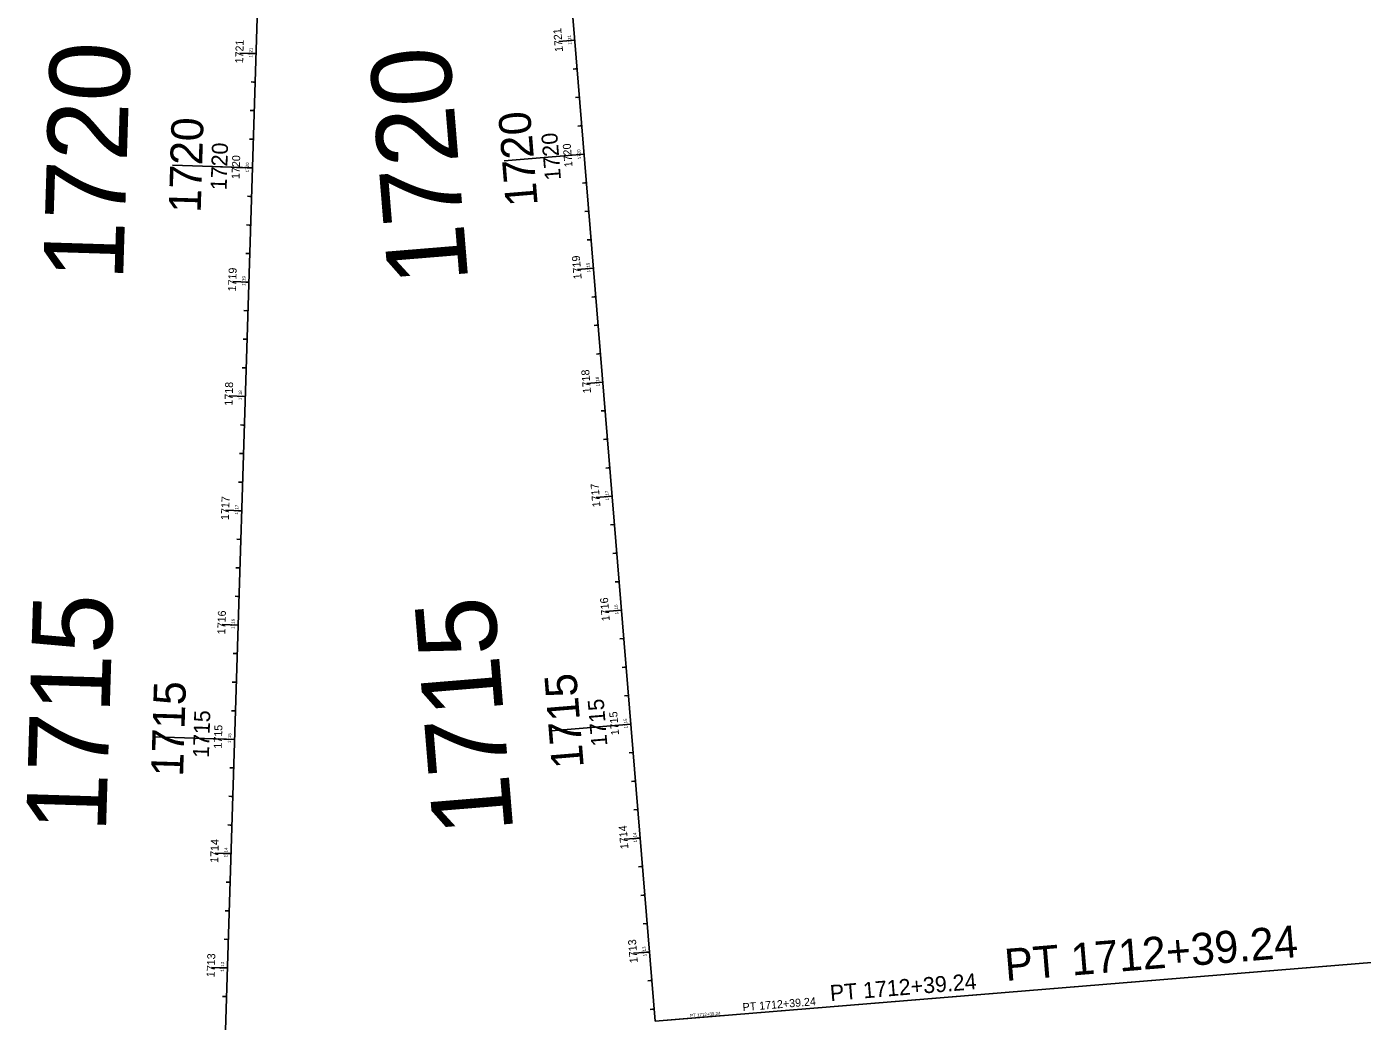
# Model space of a CAD drawing. Extents: x 353835 to 363333, y 126218 to 205387.
# Drawn here: x 361213 to 362381, y 130454 to 131324 of the extents above; entities that cross this region are included whole.
import ezdxf

# ---------------------------------------------------------------- set-up
doc = ezdxf.new("R2010")
doc.units = 0
for name, color, linetype in [('P_ALI_100_PIData', 7, 'Continuous'), ('P_ALI_100_Sta', 7, 'Continuous'), ('P_ALI_100_Tic', 7, 'Continuous'), ('P_ALI_20', 7, 'Continuous'), ('P_ALI_200_PIData', 7, 'Continuous'), ('P_ALI_200_Sta', 7, 'Continuous'), ('P_ALI_200_Tic', 7, 'Continuous'), ('P_ALI_20_PIData', 7, 'Continuous'), ('P_ALI_20_Sta', 7, 'Continuous'), ('P_ALI_20_Tic', 7, 'Continuous'), ('P_ALI_500_PIData', 7, 'Continuous'), ('P_ALI_500_Sta', 7, 'Continuous'), ('P_ALI_50_PIData', 7, 'Continuous'), ('P_ALI_50_Sta', 7, 'Continuous'), ('P_ALI_50_Tic', 7, 'Continuous')]:
    doc.layers.add(name, color=color, linetype=linetype)

msp = doc.modelspace()

# ---------------------------------------------------------------- linework, layer by layer
for points in [[(361692.5, 131312), (361692.5, 131312)], [(361708.9, 131112.6), (361708.9, 131112.6)], [(361717.1, 131013), (361717.1, 131013)], [(361725.2, 130913.3), (361725.3, 130913.3)], [(361733.4, 130813.6), (361733.4, 130813.6)], [(361749.8, 130614.3), (361749.8, 130614.3)], [(361757.9, 130514.6), (361758, 130514.6)]]:
    msp.add_lwpolyline(points)
at = {"layer": 'P_ALI_100_PIData'}
for points in [[(361762.9, 130454.1), (362061.9, 130478.6)], [(361762.9, 130454.1), (361822.7, 130459)]]:
    msp.add_lwpolyline(points, dxfattribs=at)
at = {"layer": 'P_ALI_100_Tic'}
for points in [[(361685.6, 131311.4), (361692.5, 131312)], [(361406.7, 131300.5), (361413.7, 131300.3)], [(361630.9, 131206.6), (361700.7, 131212.3)], [(361686.8, 131211.1), (361700.7, 131212.3)], [(361340.6, 131202.6), (361410.6, 131200.4)], [(361396.6, 131200.8), (361410.6, 131200.4)], [(361701.9, 131112.1), (361708.9, 131112.6)], [(361400.5, 131100.6), (361407.5, 131100.4)], [(361710.1, 131012.4), (361717.1, 131013)], [(361397.3, 131000.7), (361404.3, 131000.5)], [(361718.3, 130912.7), (361725.2, 130913.3)], [(361394.2, 130900.7), (361401.2, 130900.5)], [(361726.4, 130813.1), (361733.4, 130813.6)], [(361391.1, 130800.8), (361398.1, 130800.6)], [(361671.8, 130708.2), (361741.6, 130714)], [(361727.6, 130712.8), (361741.6, 130714)], [(361325, 130702.8), (361395, 130700.6)], [(361381, 130701.1), (361395, 130700.6)], [(361742.8, 130613.7), (361749.8, 130614.3)], [(361384.9, 130600.9), (361391.9, 130600.7)], [(361751, 130514.1), (361757.9, 130514.6)], [(361381.7, 130500.9), (361388.7, 130500.7)]]:
    msp.add_lwpolyline(points, dxfattribs=at)
at = {"layer": 'P_ALI_20'}
for p, q in [((361371.2, 129938.3), (361462, 132847.8)), ((361762.9, 130454.1), (361568.2, 132827.2))]:
    msp.add_line(p, q, dxfattribs=at)
at = {"layer": 'P_ALI_200_PIData'}
msp.add_lwpolyline([(361762.9, 130454.1), (362360.9, 130503.1)], dxfattribs=at)
at = {"layer": 'P_ALI_200_Tic'}
for points in [[(361678.6, 131310.8), (361692.5, 131312)], [(361399.7, 131300.8), (361413.7, 131300.3)], [(361672.8, 131210), (361700.7, 131212.3)], [(361382.6, 131201.3), (361410.6, 131200.4)], [(361694.9, 131111.5), (361708.9, 131112.6)], [(361393.5, 131100.9), (361407.5, 131100.4)], [(361703.1, 131011.8), (361717.1, 131013)], [(361390.3, 131000.9), (361404.3, 131000.5)], [(361711.3, 130912.1), (361725.2, 130913.3)], [(361387.2, 130901), (361401.2, 130900.5)], [(361719.5, 130812.5), (361733.4, 130813.6)], [(361384.1, 130801), (361398.1, 130800.6)], [(361713.7, 130711.7), (361741.6, 130714)], [(361367, 130701.5), (361395, 130700.6)], [(361735.8, 130613.2), (361749.8, 130614.3)], [(361377.9, 130601.1), (361391.9, 130600.7)], [(361744, 130513.5), (361757.9, 130514.6)], [(361374.7, 130501.2), (361388.7, 130500.7)]]:
    msp.add_lwpolyline(points, dxfattribs=at)
at = {"layer": 'P_ALI_20_Tic'}
for points in [[(361689.7, 131311.7), (361692.5, 131312)], [(361410.9, 131300.4), (361413.7, 131300.3)], [(361693.2, 131286.9), (361694.6, 131287)], [(361411.5, 131275.4), (361412.9, 131275.3)], [(361695.2, 131262), (361696.6, 131262.1)], [(361410.7, 131250.4), (361412.1, 131250.4)], [(361697.3, 131237.1), (361698.7, 131237.2)], [(361410, 131225.4), (361411.4, 131225.4)], [(361697.9, 131212.1), (361700.7, 131212.3)], [(361407.8, 131200.5), (361410.6, 131200.4)], [(361701.4, 131187.3), (361702.8, 131187.4)], [(361408.4, 131175.4), (361409.8, 131175.4)], [(361703.4, 131162.3), (361704.8, 131162.5)], [(361407.6, 131150.4), (361409, 131150.4)], [(361705.5, 131137.4), (361706.8, 131137.5)], [(361406.8, 131125.5), (361408.2, 131125.4)], [(361706.1, 131112.4), (361708.9, 131112.6)], [(361404.7, 131100.5), (361407.5, 131100.4)], [(361709.5, 131087.6), (361710.9, 131087.7)], [(361405.3, 131075.5), (361406.7, 131075.4)], [(361711.6, 131062.7), (361713, 131062.8)], [(361404.5, 131050.5), (361405.9, 131050.5)], [(361713.6, 131037.8), (361715, 131037.9)], [(361403.7, 131025.5), (361405.1, 131025.5)], [(361714.3, 131012.7), (361717.1, 131013)], [(361401.5, 131000.6), (361404.3, 131000.5)], [(361717.7, 130987.9), (361719.1, 130988)], [(361402.2, 130975.5), (361403.6, 130975.5)], [(361719.8, 130963), (361721.2, 130963.1)], [(361401.4, 130950.5), (361402.8, 130950.5)], [(361721.8, 130938.1), (361723.2, 130938.2)], [(361400.6, 130925.6), (361402, 130925.5)], [(361722.5, 130913.1), (361725.2, 130913.3)], [(361398.4, 130900.6), (361401.2, 130900.5)], [(361725.9, 130888.3), (361727.3, 130888.4)], [(361399, 130875.6), (361400.4, 130875.5)], [(361727.9, 130863.3), (361729.3, 130863.5)], [(361398.3, 130850.6), (361399.7, 130850.6)], [(361730, 130838.4), (361731.4, 130838.5)], [(361397.5, 130825.6), (361398.9, 130825.6)], [(361730.6, 130813.4), (361733.4, 130813.6)], [(361395.3, 130800.7), (361398.1, 130800.6)], [(361734.1, 130788.6), (361735.5, 130788.7)], [(361395.9, 130775.6), (361397.3, 130775.6)], [(361736.1, 130763.7), (361737.5, 130763.8)], [(361395.1, 130750.6), (361396.5, 130750.6)], [(361738.2, 130738.8), (361739.6, 130738.9)], [(361394.4, 130725.7), (361395.8, 130725.6)], [(361738.8, 130713.7), (361741.6, 130714)], [(361392.2, 130700.7), (361395, 130700.6)], [(361742.2, 130688.9), (361743.6, 130689)], [(361392.8, 130675.7), (361394.2, 130675.6)], [(361744.3, 130664), (361745.7, 130664.1)], [(361392, 130650.7), (361393.4, 130650.6)], [(361746.3, 130639.1), (361747.7, 130639.2)], [(361391.2, 130625.7), (361392.6, 130625.7)], [(361747, 130614.1), (361749.8, 130614.3)], [(361389.1, 130600.8), (361391.9, 130600.7)], [(361750.4, 130589.3), (361751.8, 130589.4)], [(361389.7, 130575.7), (361391.1, 130575.7)], [(361752.5, 130564.4), (361753.9, 130564.5)], [(361388.9, 130550.7), (361390.3, 130550.7)], [(361754.5, 130539.4), (361755.9, 130539.5)], [(361388.1, 130525.8), (361389.5, 130525.7)], [(361755.2, 130514.4), (361757.9, 130514.6)], [(361385.9, 130500.8), (361388.7, 130500.7)], [(361758.6, 130489.6), (361760, 130489.7)], [(361386.6, 130475.8), (361388, 130475.7)], [(361760.6, 130464.7), (361762, 130464.8)]]:
    msp.add_lwpolyline(points, dxfattribs=at)
at = {"layer": 'P_ALI_500_PIData'}
msp.add_lwpolyline([(361762.9, 130454.1), (363257.9, 130576.7)], dxfattribs=at)
at = {"layer": 'P_ALI_50_PIData'}
msp.add_lwpolyline([(361762.9, 130454.1), (361912.4, 130466.3)], dxfattribs=at)
at = {"layer": 'P_ALI_50_Tic'}
for points in [[(361685.6, 131311.4), (361692.5, 131312)], [(361406.7, 131300.5), (361413.7, 131300.3)], [(361406.7, 131300.5), (361413.7, 131300.3)], [(361691.1, 131286.8), (361694.6, 131287)], [(361409.4, 131275.5), (361412.9, 131275.3)], [(361409.4, 131275.5), (361412.9, 131275.3)], [(361693.1, 131261.8), (361696.6, 131262.1)], [(361408.6, 131250.5), (361412.1, 131250.4)], [(361408.6, 131250.5), (361412.1, 131250.4)], [(361695.2, 131236.9), (361698.7, 131237.2)], [(361407.9, 131225.5), (361411.4, 131225.4)], [(361407.9, 131225.5), (361411.4, 131225.4)], [(361693.7, 131211.7), (361700.7, 131212.3)], [(361403.6, 131200.6), (361410.6, 131200.4)], [(361403.6, 131200.6), (361410.6, 131200.4)], [(361699.3, 131187.1), (361702.8, 131187.4)], [(361406.3, 131175.5), (361409.8, 131175.4)], [(361406.3, 131175.5), (361409.8, 131175.4)], [(361701.3, 131162.2), (361704.8, 131162.5)], [(361405.5, 131150.5), (361409, 131150.4)], [(361405.5, 131150.5), (361409, 131150.4)], [(361703.4, 131137.3), (361706.8, 131137.5)], [(361404.7, 131125.5), (361408.2, 131125.4)], [(361404.7, 131125.5), (361408.2, 131125.4)], [(361701.9, 131112.1), (361708.9, 131112.6)], [(361400.5, 131100.6), (361407.5, 131100.4)], [(361400.5, 131100.6), (361407.5, 131100.4)], [(361707.4, 131087.4), (361710.9, 131087.7)], [(361403.2, 131075.6), (361406.7, 131075.4)], [(361403.2, 131075.6), (361406.7, 131075.4)], [(361709.5, 131062.5), (361713, 131062.8)], [(361402.4, 131050.6), (361405.9, 131050.5)], [(361402.4, 131050.6), (361405.9, 131050.5)], [(361711.5, 131037.6), (361715, 131037.9)], [(361401.6, 131025.6), (361405.1, 131025.5)], [(361401.6, 131025.6), (361405.1, 131025.5)], [(361710.1, 131012.4), (361717.1, 131013)], [(361397.3, 131000.7), (361404.3, 131000.5)], [(361397.3, 131000.7), (361404.3, 131000.5)], [(361715.6, 130987.8), (361719.1, 130988)], [(361400.1, 130975.6), (361403.6, 130975.5)], [(361400.1, 130975.6), (361403.6, 130975.5)], [(361717.7, 130962.8), (361721.2, 130963.1)], [(361399.3, 130950.6), (361402.8, 130950.5)], [(361399.3, 130950.6), (361402.8, 130950.5)], [(361719.7, 130937.9), (361723.2, 130938.2)], [(361398.5, 130925.6), (361402, 130925.5)], [(361398.5, 130925.6), (361402, 130925.5)], [(361718.3, 130912.7), (361725.2, 130913.3)], [(361394.2, 130900.7), (361401.2, 130900.5)], [(361394.2, 130900.7), (361401.2, 130900.5)], [(361723.8, 130888.1), (361727.3, 130888.4)], [(361396.9, 130875.6), (361400.4, 130875.5)], [(361396.9, 130875.6), (361400.4, 130875.5)], [(361725.8, 130863.2), (361729.3, 130863.5)], [(361396.2, 130850.7), (361399.7, 130850.6)], [(361396.2, 130850.7), (361399.7, 130850.6)], [(361727.9, 130838.3), (361731.4, 130838.5)], [(361395.4, 130825.7), (361398.9, 130825.6)], [(361395.4, 130825.7), (361398.9, 130825.6)], [(361726.4, 130813.1), (361733.4, 130813.6)], [(361391.1, 130800.8), (361398.1, 130800.6)], [(361391.1, 130800.8), (361398.1, 130800.6)], [(361732, 130788.4), (361735.5, 130788.7)], [(361393.8, 130775.7), (361397.3, 130775.6)], [(361393.8, 130775.7), (361397.3, 130775.6)], [(361734, 130763.5), (361737.5, 130763.8)], [(361393, 130750.7), (361396.5, 130750.6)], [(361393, 130750.7), (361396.5, 130750.6)], [(361736.1, 130738.6), (361739.6, 130738.9)], [(361392.3, 130725.7), (361395.8, 130725.6)], [(361392.3, 130725.7), (361395.8, 130725.6)], [(361734.6, 130713.4), (361741.6, 130714)], [(361388, 130700.8), (361395, 130700.6)], [(361388, 130700.8), (361395, 130700.6)], [(361740.2, 130688.8), (361743.6, 130689)], [(361390.7, 130675.7), (361394.2, 130675.6)], [(361390.7, 130675.7), (361394.2, 130675.6)], [(361742.2, 130663.8), (361745.7, 130664.1)], [(361389.9, 130650.8), (361393.4, 130650.6)], [(361389.9, 130650.8), (361393.4, 130650.6)], [(361744.2, 130638.9), (361747.7, 130639.2)], [(361389.1, 130625.8), (361392.6, 130625.7)], [(361389.1, 130625.8), (361392.6, 130625.7)], [(361742.8, 130613.7), (361749.8, 130614.3)], [(361384.9, 130600.9), (361391.9, 130600.7)], [(361384.9, 130600.9), (361391.9, 130600.7)], [(361748.3, 130589.1), (361751.8, 130589.4)], [(361387.6, 130575.8), (361391.1, 130575.7)], [(361387.6, 130575.8), (361391.1, 130575.7)], [(361750.4, 130564.2), (361753.9, 130564.5)], [(361386.8, 130550.8), (361390.3, 130550.7)], [(361386.8, 130550.8), (361390.3, 130550.7)], [(361752.4, 130539.3), (361755.9, 130539.5)], [(361386, 130525.8), (361389.5, 130525.7)], [(361386, 130525.8), (361389.5, 130525.7)], [(361751, 130514.1), (361757.9, 130514.6)], [(361381.7, 130500.9), (361388.7, 130500.7)], [(361381.7, 130500.9), (361388.7, 130500.7)], [(361756.5, 130489.4), (361760, 130489.7)], [(361384.5, 130475.8), (361388, 130475.7)], [(361384.5, 130475.8), (361388, 130475.7)], [(361758.5, 130464.5), (361762, 130464.8)]]:
    msp.add_lwpolyline(points, dxfattribs=at)

# ---------------------------------------------------------------- texts
at = {"layer": 'P_ALI_100_PIData'}
msp.add_text('PT 1712+39.24', height=14, rotation=4.6898, dxfattribs=at).set_placement((361916.3, 130471.7))
at = {"layer": 'P_ALI_100_Sta'}
for s, rotation, p in [('1720', 94.6898, (361680.5, 131190.1)), ('1720', 88.2122, (361388, 131180.6)), ('1715', 94.6898, (361721.1, 130695.1)), ('1715', 88.2122, (361372.5, 130684.2))]:
    msp.add_text(s, height=14, rotation=rotation, dxfattribs=at).set_placement(p)
at = {"layer": 'P_ALI_200_PIData'}
msp.add_text('PT 1712+39.24', height=28, rotation=4.6898, dxfattribs=at).set_placement((362069.6, 130489.3))
at = {"layer": 'P_ALI_200_Sta'}
for s, rotation, p in [('1720', 94.6898, (361660.2, 131167.8)), ('1720', 88.2122, (361365.3, 131160.8)), ('1715', 94.6898, (361700.5, 130676.3)), ('1715', 88.2122, (361349.9, 130667.8))]:
    msp.add_text(s, height=28, rotation=rotation, dxfattribs=at).set_placement(p)
at = {"layer": 'P_ALI_20_PIData'}
msp.add_text('PT 1712+39.24', height=2.8, rotation=4.6898, dxfattribs=at).set_placement((361793.6, 130457.6))
at = {"layer": 'P_ALI_20_Sta'}
for s, rotation, p in [('1721', 94.6898, (361689.8, 131308.1)), ('1721', 88.2122, (361410.5, 131296.8)), ('1720', 94.6898, (361698, 131208)), ('1720', 88.2122, (361407.4, 131196.4)), ('1719', 94.6898, (361706.1, 131109)), ('1719', 88.2122, (361404.3, 131097.1)), ('1718', 94.6898, (361714.3, 131009.3)), ('1718', 88.2122, (361401.2, 130997.2)), ('1717', 94.6898, (361722.5, 130909.6)), ('1717', 88.2122, (361398, 130897.2)), ('1716', 94.6898, (361730.6, 130810)), ('1716', 88.2122, (361394.9, 130797.3)), ('1715', 94.6898, (361738.8, 130710.3)), ('1715', 88.2122, (361391.8, 130697.3)), ('1714', 94.6898, (361747, 130610.6)), ('1714', 88.2122, (361388.7, 130597.4)), ('1713', 94.6898, (361755.2, 130511)), ('1713', 88.2122, (361385.6, 130497.4))]:
    msp.add_text(s, height=2.8, rotation=rotation, dxfattribs=at).set_placement(p)
at = {"layer": 'P_ALI_500_Sta'}
for s, rotation, p in [('1720', 88.2122, (361297.4, 131101.3)), ('1720', 94.6898, (361599.5, 131101.1)), ('1715', 88.2122, (361282.4, 130618.7)), ('1715', 94.6898, (361638.9, 130619.8))]:
    msp.add_text(s, height=70, rotation=rotation, dxfattribs=at).set_placement(p)
at = {"layer": 'P_ALI_50_PIData'}
msp.add_text('PT 1712+39.24', height=7, rotation=4.6898, dxfattribs=at).set_placement((361839.6, 130462.9))
at = {"layer": 'P_ALI_50_Sta'}
for s, rotation, p in [('1721', 94.6898, (361682.3, 131302)), ('1721', 88.2122, (361402.4, 131291.6)), ('1721', 88.2122, (361402.4, 131291.6)), ('1720', 94.6898, (361690.6, 131201.2)), ('1720', 88.2122, (361399.3, 131190.5)), ('1720', 88.2122, (361399.3, 131190.5)), ('1719', 94.6898, (361698.6, 131103.2)), ('1719', 88.2122, (361396.2, 131092.2)), ('1719', 88.2122, (361396.2, 131092.2)), ('1718', 94.6898, (361706.8, 131003.5)), ('1718', 88.2122, (361393.1, 130992.3)), ('1718', 88.2122, (361393.1, 130992.3)), ('1717', 94.6898, (361715, 130903.9)), ('1717', 88.2122, (361390, 130892.3)), ('1717', 88.2122, (361390, 130892.3)), ('1716', 94.6898, (361723.2, 130804.2)), ('1716', 88.2122, (361386.8, 130792.4)), ('1716', 88.2122, (361386.8, 130792.4)), ('1715', 94.6898, (361731.3, 130704.5)), ('1715', 88.2122, (361383.7, 130692.4)), ('1715', 88.2122, (361383.7, 130692.4)), ('1714', 94.6898, (361739.5, 130604.9)), ('1714', 88.2122, (361380.6, 130592.5)), ('1714', 88.2122, (361380.6, 130592.5)), ('1713', 94.6898, (361747.7, 130505.2)), ('1713', 88.2122, (361377.5, 130492.5)), ('1713', 88.2122, (361377.5, 130492.5))]:
    msp.add_text(s, height=7, rotation=rotation, dxfattribs=at).set_placement(p)

doc.saveas('drawing.dxf')
